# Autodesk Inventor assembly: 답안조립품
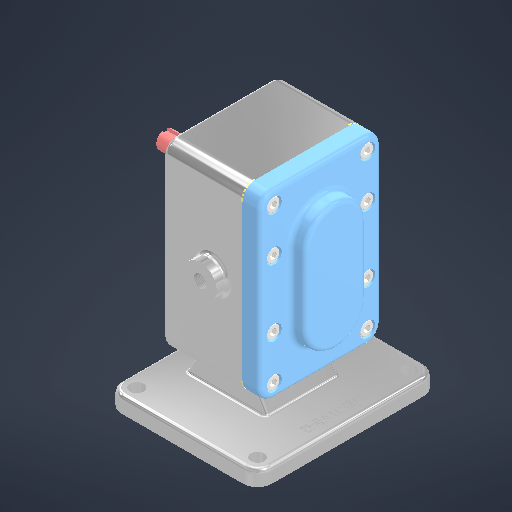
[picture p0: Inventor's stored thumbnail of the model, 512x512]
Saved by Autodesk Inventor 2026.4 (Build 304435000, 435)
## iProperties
Created: 2026-10
Part Number: 답안조립품
Document SubType Name: Assembly
Designer: user
Author: user
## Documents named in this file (11)
- C:\Users\user\Desktop\761003V1013\답안조립품.iam
- C:\Users\user\Desktop\761003V1013\부품.ipt
- C:\Users\user\Desktop\761003V1013\6각 구멍붙이 볼트 M5x16\6각 구멍붙이 볼트 M5x16.ipt
- C:\Users\user\Desktop\761003V1013\개스킷\개스킷.ipt
- C:\Users\user\Desktop\761003V1013\구동 축\구동 축.ipt
- C:\Users\user\Desktop\761003V1013\베어링 부시\베어링 부시.ipt
- C:\Users\user\Desktop\761003V1013\스퍼 기어\스퍼 기어.ipt
- C:\Users\user\Desktop\761003V1013\오일 실 16 28 7\오일 실 16 28 7.ipt
- C:\Users\user\Desktop\761003V1013\종동 축\종동 축.ipt
- C:\Users\user\Desktop\761003V1013\커버\커버.ipt
- C:\Users\user\Desktop\761003V1013\평행 키 6x6x18\평행 키 6x6x18.ipt
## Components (10 placed, 3 different names)
1. 6각 구멍붙이 볼트 M5x16:1
2. 개스킷:1 — 각도:4
3. 구동 축:1 — 각도:3
4. 6각 구멍붙이 볼트 M5x16:2
5. 6각 구멍붙이 볼트 M5x16:3
6. 6각 구멍붙이 볼트 M5x16:4
7. 6각 구멍붙이 볼트 M5x16:5
8. 6각 구멍붙이 볼트 M5x16:6
9. 6각 구멍붙이 볼트 M5x16:7
10. 6각 구멍붙이 볼트 M5x16:8
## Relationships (2: Angle 2)
- 각도:3 [Angle]: 구동 축:1
- 각도:4 [Angle]: 개스킷:1
